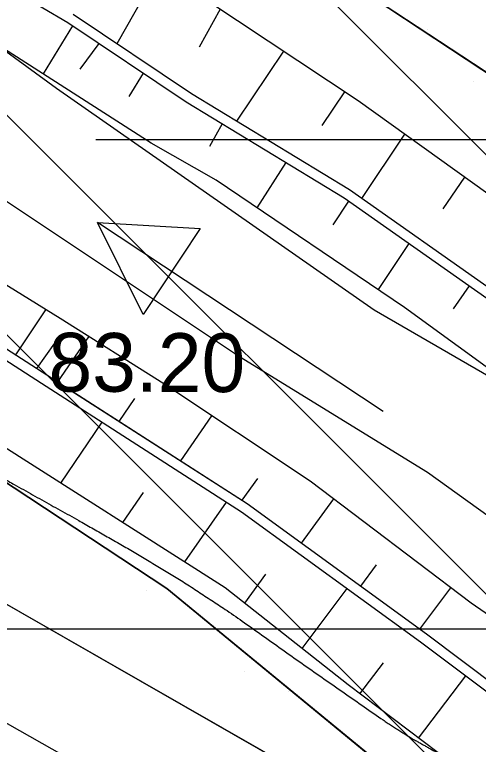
# Model space of a CAD drawing. Extents: x 417995 to 421451, y 4454518 to 4458015.
# Drawn here: x 420624.2 to 420671.5, y 4456645.1 to 4456719.7 of the extents above; entities that cross this region are included whole.
import ezdxf

# ---------------------------------------------------------------- set-up
doc = ezdxf.new("R2010")
doc.units = 0
for name, color, linetype in [('ADAKENARI', 7, 'Continuous'), ('Default', 7, 'Continuous'), ('Egri_1m', 7, 'Continuous'), ('Hid_Dere_Sulu_Yat_Gen', 7, 'Continuous'), ('PL_AYA_PARK_DINLENME', 7, 'Continuous'), ('PL_TA_K_DERE', 7, 'Continuous'), ('S_Istikamet_Oku', 7, 'Continuous'), ('Sev_Sevalti', 7, 'Continuous'), ('Sev_Sevustu', 7, 'Continuous'), ('Sev_Tarama', 7, 'Continuous'), ('Sinir_Ist_Duvari', 7, 'Continuous'), ('SN_TR_SIVILASMA', 7, 'Continuous'), ('SN_TR_TASKIN', 7, 'Continuous'), ('TR_PARKALANI', 7, 'Continuous'), ('TRFAT_PARKALANI', 7, 'Continuous'), ('Y_Kot_Noktasi', 7, 'Continuous')]:
    doc.layers.add(name, color=color, linetype=linetype)

# ---------------------------------------------------------------- blocks, each defined once
blk = doc.blocks.new('POINT_DISPLAY')
at = {"layer": 'Default'}
blk.add_line((0, 0), (0, 0), dxfattribs=at)

msp = doc.modelspace()

# ---------------------------------------------------------------- linework, layer by layer
at = {"layer": 'ADAKENARI'}
for p, q in [((420676.56, 4456710.964), (420603.968, 4456758.881)), ((420657.58, 4456639.752), (420530.801, 4456712.428)), ((420572.513, 4456705.355), (420639.693, 4456661.01)), ((420639.693, 4456661.01), (420701.864, 4456609.89))]:
    msp.add_line(p, q, dxfattribs=at)
msp.add_arc((420191.407, 4456074.797), 823.132, 35.35416, 63.79989, dxfattribs=at)
at = {"layer": 'Egri_1m'}
msp.add_spline([(420621.537, 4456673.14), (420621.822, 4456672.974), (420622.106, 4456672.809), (420622.39, 4456672.643), (420622.675, 4456672.477), (420622.96, 4456672.313), (420623.245, 4456672.148), (420623.53, 4456671.984), (420624.116, 4456671.652), (420625.055, 4456671.125), (420625.993, 4456670.598), (420626.931, 4456670.071), (420627.871, 4456669.546), (420628.811, 4456669.023), (420629.752, 4456668.5), (420630.693, 4456667.977), (420632.043, 4456667.206), (420633.429, 4456666.415), (420634.814, 4456665.623), (420636.196, 4456664.826), (420637.564, 4456664.005), (420638.931, 4456663.183), (420640.299, 4456662.361), (420641.674, 4456661.504), (420643.062, 4456660.591), (420644.45, 4456659.679), (420645.838, 4456658.766), (420647.622, 4456657.527), (420649.654, 4456656.084), (420651.686, 4456654.641), (420653.719, 4456653.198), (420655.762, 4456651.771), (420657.807, 4456650.347), (420659.852, 4456648.923), (420661.773, 4456647.587), (420662.198, 4456647.304), (420662.623, 4456647.022), (420663.048, 4456646.739), (420663.476, 4456646.462), (420663.911, 4456646.196), (420664.345, 4456645.929), (420664.78, 4456645.663), (420665.165, 4456645.437), (420665.507, 4456645.246), (420665.848, 4456645.055), (420666.19, 4456644.864), (420666.532, 4456644.672), (420666.873, 4456644.481), (420667.215, 4456644.29), (420667.557, 4456644.099)], degree=3, dxfattribs=at)
at = {"layer": 'Hid_Dere_Sulu_Yat_Gen'}
for points in [[(420628.797, 4456688.609), (420599.698, 4456706.626), (420583.742, 4456714.826), (420566.175, 4456723.317), (420547.914, 4456733.544), (420531.197, 4456742.218), (420514.496, 4456749.85), (420494.365, 4456759.328), (420473.739, 4456768.619), (420453.913, 4456778.395), (420430.949, 4456789.191), (420417.662, 4456796.02), (420400.799, 4456803.873), (420384.502, 4456813.366), (420364.611, 4456824.706), (420355.916, 4456828.361), (420344.654, 4456832.529)], [(420638.098, 4456706.537), (420610.182, 4456724.455), (420579.701, 4456740.59), (420553.415, 4456754.926), (420529.698, 4456766.467), (420508.916, 4456775.976), (420484.056, 4456788.077), (420475.421, 4456791.95), (420471.324, 4456797.697)], [(420788.841, 4456575.261), (420772.879, 4456595.083), (420753.392, 4456615.444), (420729.407, 4456638.507), (420709.417, 4456655.64), (420685.876, 4456673.795), (420663.953, 4456689.741), (420644.724, 4456702.749), (420638.098, 4456706.537)], [(420628.646, 4456688.703), (420628.674, 4456688.757)], [(420788.704, 4456562.233), (420779.24, 4456572.915), (420773.131, 4456578.235), (420770.955, 4456579.857), (420768.725, 4456581.48), (420764.492, 4456585.129), (420760.701, 4456587.707), (420757.161, 4456589.192), (420754.18, 4456591.373), (420749.559, 4456594.647), (420742.315, 4456600.313), (420735.178, 4456605.841), (420725.727, 4456615.524), (420721.547, 4456619.007), (420706.863, 4456631.377), (420698.027, 4456639.143), (420687.173, 4456648.173), (420670.751, 4456659.516), (420654.326, 4456672.002), (420639.374, 4456681.928), (420628.797, 4456688.609)]]:
    msp.add_lwpolyline(points, dxfattribs=at)
at = {"layer": 'PL_AYA_PARK_DINLENME'}
msp.add_lwpolyline([(420398.451, 4456770.435), (420341.542, 4456780.97), (420343.747, 4456814.103), (420500.975, 4456742.521), (420572.513, 4456705.355), (420639.693, 4456661.01), (420701.864, 4456609.89), (420758.351, 4456552.552), (420808.535, 4456489.624), (420852.304, 4456421.109), (420929.964, 4456284.244), (420924.233, 4456280.992), (420830.138, 4456440.665), (420780.571, 4456521.605), (420657.58, 4456639.752), (420530.801, 4456712.428), (420483.239, 4456735.932), (420462.904, 4456746.949), (420444.362, 4456753.772)], close=True, dxfattribs=at)
for points in [[(420413.737, 4456796.23), (420457.309, 4456777.768), (420497.188, 4456760.043), (420547.406, 4456742.319), (420585.808, 4456724.595), (420620.518, 4456702.44), (420647.104, 4456684.716), (420666.305, 4456672.9), (420689.937, 4456655.915), (420715.785, 4456636.713), (420731.294, 4456611.604), (420747.541, 4456592.403), (420806.621, 4456538.493), (420839.115, 4456497.136)], [(420778.06, 4456586.457), (420756.719, 4456604.952), (420739.361, 4456629.102), (420719.74, 4456647.969), (420684.27, 4456675.892), (420660.875, 4456689.476), (420628.424, 4456712.116), (420597.482, 4456734.756), (420571.069, 4456750.604)]]:
    msp.add_lwpolyline(points, dxfattribs=at)
at = {"layer": 'PL_TA_K_DERE'}
msp.add_lwpolyline([(420859.034, 4456525.74), (420905.427, 4456453.119), (420983.888, 4456314.841), (420929.964, 4456284.244), (420852.304, 4456421.109), (420808.535, 4456489.624), (420758.351, 4456552.552), (420701.864, 4456609.89), (420639.693, 4456661.01), (420572.513, 4456705.355), (420500.975, 4456742.521), (420343.747, 4456814.103), (420348.148, 4456880.222), (420452.948, 4456832.51), (420528.13, 4456798.281), (420603.968, 4456758.881), (420676.56, 4456710.964), (420743.751, 4456655.717), (420804.798, 4456593.749)], close=True, dxfattribs=at)
for points in [[(420413.737, 4456796.23), (420457.309, 4456777.768), (420497.188, 4456760.043), (420547.406, 4456742.319), (420585.808, 4456724.595), (420620.518, 4456702.44), (420647.104, 4456684.716), (420666.305, 4456672.9), (420689.937, 4456655.915), (420715.785, 4456636.713), (420731.294, 4456611.604), (420747.541, 4456592.403), (420806.621, 4456538.493), (420839.115, 4456497.136)], [(420778.06, 4456586.457), (420756.719, 4456604.952), (420739.361, 4456629.102), (420719.74, 4456647.969), (420684.27, 4456675.892), (420660.875, 4456689.476), (420628.424, 4456712.116), (420597.482, 4456734.756), (420571.069, 4456750.604)]]:
    msp.add_lwpolyline(points, dxfattribs=at)
at = {"layer": 'S_Istikamet_Oku'}
for p, q in [((420661.777, 4456679.094), (420632.61, 4456698.44)), ((420637.292, 4456689.035), (420632.61, 4456698.44)), ((420632.61, 4456698.44), (420643.105, 4456697.799)), ((420643.105, 4456697.799), (420637.292, 4456689.035)), ((420642.862, 4456697.814), (420642.862, 4456697.814)), ((420642.862, 4456697.814), (420642.862, 4456697.814))]:
    msp.add_line(p, q, dxfattribs=at)
at = {"layer": 'Sev_Sevalti'}
for points in [[(420628.797, 4456688.609), (420599.698, 4456706.626), (420583.742, 4456714.826), (420566.175, 4456723.317), (420547.914, 4456733.544), (420531.197, 4456742.218), (420514.496, 4456749.85), (420494.365, 4456759.328), (420473.739, 4456768.619), (420453.913, 4456778.395), (420430.949, 4456789.191), (420417.662, 4456796.02), (420400.799, 4456803.873), (420384.502, 4456813.366), (420364.611, 4456824.706)], [(420638.098, 4456706.537), (420610.182, 4456724.455), (420579.701, 4456740.59), (420553.415, 4456754.926), (420529.698, 4456766.467), (420508.916, 4456775.976), (420484.056, 4456788.077), (420475.421, 4456791.95), (420471.324, 4456797.697)], [(420778.377, 4456600.24), (420771.137, 4456608.123), (420758.577, 4456621.315), (420745.375, 4456633.729), (420734.226, 4456643.899), (420716.857, 4456658.478), (420706.462, 4456666.893), (420688.714, 4456680.367), (420672.941, 4456691.487), (420658.335, 4456701.751), (420642.215, 4456711.569), (420630.144, 4456719.673)], [(420570.248, 4456715.118), (420576.457, 4456711.886), (420584.562, 4456707.668), (420588.732, 4456705.255), (420600.85, 4456698.245), (420606.909, 4456694.74), (420612.821, 4456691.086), (420618.705, 4456687.294), (420626.887, 4456682.022)], [(420788.841, 4456575.261), (420772.879, 4456595.083), (420753.392, 4456615.444), (420729.407, 4456638.507), (420709.417, 4456655.64), (420685.876, 4456673.795), (420663.953, 4456689.741), (420644.724, 4456702.749), (420638.098, 4456706.537)], [(420788.704, 4456562.233), (420779.24, 4456572.915), (420773.131, 4456578.235), (420770.955, 4456579.857), (420768.725, 4456581.48), (420764.492, 4456585.129), (420760.701, 4456587.707), (420757.161, 4456589.192), (420754.18, 4456591.373), (420749.559, 4456594.647), (420742.315, 4456600.313), (420735.178, 4456605.841), (420725.727, 4456615.524), (420721.547, 4456619.007), (420706.863, 4456631.377), (420698.027, 4456639.143), (420687.173, 4456648.173), (420670.751, 4456659.516), (420654.326, 4456672.002), (420639.374, 4456681.928), (420628.797, 4456688.609)], [(420626.884, 4456682.017), (420647.322, 4456668.865), (420665.603, 4456655.57), (420683.864, 4456641.83), (420699.977, 4456629.29), (420717.414, 4456613.548), (420732.646, 4456599.297), (420742.444, 4456589.861), (420751.336, 4456580.564), (420753.319, 4456578.59), (420756.674, 4456576.51)]]:
    msp.add_lwpolyline(points, dxfattribs=at)
at = {"layer": 'Sev_Sevustu'}
for points in [[(420756.674, 4456576.51), (420749.74, 4456576.3), (420745.366, 4456577.634), (420723.44, 4456596.246), (420707.878, 4456611.316), (420696.19, 4456623.438), (420679.958, 4456634.943), (420668.92, 4456643.069), (420658.207, 4456651.162), (420645.633, 4456661.106), (420621.906, 4456676.224), (420610.056, 4456683.119), (420601.456, 4456689.735), (420590.016, 4456696.784), (420575.565, 4456703.811), (420553.678, 4456714.693), (420538.266, 4456722.751), (420518.926, 4456733.391), (420497.664, 4456743.095), (420475.49, 4456754.119), (420458.863, 4456763.31), (420439.862, 4456772.581), (420423.667, 4456781.357), (420412.251, 4456787.953)], [(420778.377, 4456600.24), (420784.051, 4456605.761), (420771.589, 4456617.935), (420760.168, 4456630.523), (420746.1, 4456645.169), (420730.801, 4456658.049), (420726.052, 4456663.537), (420720.732, 4456667.681), (420714.959, 4456672.268), (420705.806, 4456677.57), (420693.56, 4456685.671), (420679.197, 4456696.525), (420659.229, 4456710.851), (420637.713, 4456725.178), (420600.51, 4456748.944), (420578.405, 4456762.119), (420561.761, 4456771.087), (420543.627, 4456778.431), (420531.152, 4456784.596)], [(420788.967, 4456587.229), (420770.407, 4456607.44), (420757.872, 4456620.605), (420744.696, 4456632.995), (420733.567, 4456643.146), (420716.221, 4456657.706), (420705.845, 4456666.105), (420688.124, 4456679.56), (420672.366, 4456690.669), (420657.786, 4456700.914), (420641.676, 4456710.726), (420629.586, 4456718.843), (420596.383, 4456738.346), (420565.706, 4456754.073), (420534.585, 4456769.203), (420503.082, 4456784.309)], [(420563.981, 4456719.507), (420585.022, 4456708.557), (420609.77, 4456694.24), (420627.451, 4456682.849), (420627.602, 4456682.751), (420627.623, 4456682.738), (420647.891, 4456669.696), (420666.201, 4456656.38), (420684.475, 4456642.63), (420700.624, 4456630.062), (420718.095, 4456614.289), (420733.339, 4456600.027), (420743.157, 4456590.571), (420752.054, 4456581.269), (420753.948, 4456579.385), (420754.96, 4456578.757), (420758.904, 4456577.432), (420763.283, 4456574.491), (420765.073, 4456572.824), (420775.619, 4456563.863), (420788.599, 4456552.231)], [(420573.873, 4456681.562), (420577.423, 4456680.002), (420581.804, 4456677.912), (420586.138, 4456674.873), (420589.071, 4456672.349), (420590.96, 4456670.496), (420593.361, 4456668.471), (420596.406, 4456666.108), (420599.176, 4456663.533), (420601.308, 4456661.622), (420610.291, 4456654.996), (420618.814, 4456649.816), (420629.196, 4456643.923)]]:
    msp.add_lwpolyline(points, dxfattribs=at)
at = {"layer": 'Sev_Tarama'}
for p, q in [((420638.909, 4456724.382), (420634.605, 4456716.677)), ((420645.151, 4456720.226), (420642.992, 4456716.361)), ((420630.051, 4456718.531), (420627.06, 4456713.622)), ((420632.739, 4456716.726), (420630.817, 4456714.095)), ((420651.589, 4456715.938), (420646.799, 4456708.777)), ((420637.279, 4456713.678), (420635.81, 4456711.313)), ((420657.831, 4456711.781), (420655.521, 4456708.326)), ((420645.332, 4456708.499), (420644.045, 4456706.187)), ((420663.965, 4456707.453), (420659.56, 4456700.889)), ((420651.828, 4456704.543), (420648.88, 4456699.938)), ((420670.082, 4456703.064), (420667.867, 4456699.837)), ((420658.228, 4456700.604), (420656.65, 4456698.176)), ((420664.382, 4456696.279), (420661.257, 4456691.565)), ((420670.544, 4456691.949), (420668.939, 4456689.616)), ((420624.276, 4456684.894), (420627.328, 4456689.518)), ((420628.551, 4456682.141), (420631.737, 4456686.752)), ((420626.426, 4456683.509), (420628.264, 4456686.093)), ((420634.836, 4456678.096), (420636.428, 4456680.44)), ((420641.12, 4456674.053), (420644.3, 4456678.658)), ((420628.881, 4456671.78), (420633.106, 4456678.013)), ((420647.368, 4456670.033), (420648.974, 4456672.261)), ((420635.201, 4456667.753), (420637.316, 4456670.848)), ((420641.514, 4456663.73), (420645.776, 4456669.86)), ((420653.437, 4456665.662), (420656.73, 4456670.175)), ((420659.493, 4456661.258), (420661.1, 4456663.445)), ((420647.656, 4456659.506), (420649.817, 4456662.492)), ((420653.51, 4456654.876), (420658.108, 4456661.021)), ((420665.528, 4456656.869), (420668.692, 4456661.081)), ((420659.412, 4456650.251), (420661.796, 4456653.428)), ((420665.381, 4456645.742), (420670.222, 4456652.095))]:
    msp.add_line(p, q, dxfattribs=at)
at = {"layer": 'Sinir_Ist_Duvari'}
for points in [[(420629.586, 4456718.843), (420596.383, 4456738.346), (420565.706, 4456754.073), (420534.585, 4456769.203), (420503.082, 4456784.309), (420491.737, 4456791.324), (420482.075, 4456797.254), (420479.905, 4456798.672), (420479.643, 4456799.687), (420479.647, 4456800.071), (420479.736, 4456800.699), (420479.988, 4456801.271), (420481.073, 4456802.957), (420505.711, 4456819.122), (420544.345, 4456842.997), (420572.721, 4456861.066), (420593.658, 4456873.63)], [(420344.231, 4456826.108), (420352.997, 4456821.85), (420361.032, 4456818.341), (420377.241, 4456809.018), (420391.824, 4456801.083), (420405.085, 4456794.915), (420418.211, 4456788.968), (420438.453, 4456780.507), (420454.168, 4456773.437), (420472.705, 4456764.282), (420491.628, 4456755.314), (420513.735, 4456744.751), (420533.252, 4456735.065), (420563.981, 4456719.507), (420585.044, 4456708.544), (420609.792, 4456694.228), (420627.428, 4456682.863)], [(420777.64, 4456599.563), (420770.407, 4456607.44), (420757.872, 4456620.605), (420744.696, 4456632.995), (420733.567, 4456643.146), (420716.221, 4456657.706), (420705.845, 4456666.105), (420688.124, 4456679.56), (420672.366, 4456690.669), (420657.786, 4456700.914), (420641.676, 4456710.726), (420629.586, 4456718.843)], [(420627.428, 4456682.863), (420647.891, 4456669.696), (420666.201, 4456656.38), (420684.475, 4456642.63), (420700.624, 4456630.062), (420718.095, 4456614.289), (420733.339, 4456600.027), (420743.157, 4456590.571), (420752.054, 4456581.269), (420753.948, 4456579.385), (420755.667, 4456578.319), (420755.666, 4456584.922)]]:
    msp.add_lwpolyline(points, dxfattribs=at)
at = {"layer": 'SN_TR_SIVILASMA'}
for p, q in [((421277.884, 4456099.75), (419987.888, 4457389.746)), ((421277.42, 4456055.312), (419975.727, 4457357.006)), ((421277.189, 4456033.093), (419969.646, 4457340.635))]:
    msp.add_line(p, q, dxfattribs=at)
at = {"layer": 'SN_TR_TASKIN'}
for p, q in [((420632.431, 4456706.904), (420732.431, 4456706.904)), ((420582.431, 4456656.904), (420682.431, 4456656.904))]:
    msp.add_line(p, q, dxfattribs=at)
at = {"layer": 'TRFAT_PARKALANI'}
for p, q in [((420637.583, 4456660.844), (420637.583, 4456660.844)), ((420630.657, 4456656.907), (420630.657, 4456656.907)), ((420647.637, 4456652.53), (420647.637, 4456652.53)), ((420652.09, 4456650.532), (420652.09, 4456650.532))]:
    msp.add_line(p, q, dxfattribs=at)

# ---------------------------------------------------------------- block references
at = {"layer": 'TR_PARKALANI', "xscale": 0.1, "yscale": 0.10000000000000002}
for p in [(420666.337, 4456718.163), (420671.035, 4456712.799)]:
    msp.add_blockref('POINT_DISPLAY', p, dxfattribs=at)

# ---------------------------------------------------------------- texts
at = {"layer": 'Y_Kot_Noktasi'}
msp.add_text('83.20', height=6, rotation=359.81742, dxfattribs=at).set_placement((420627.61, 4456681.154))

doc.saveas('drawing.dxf')
